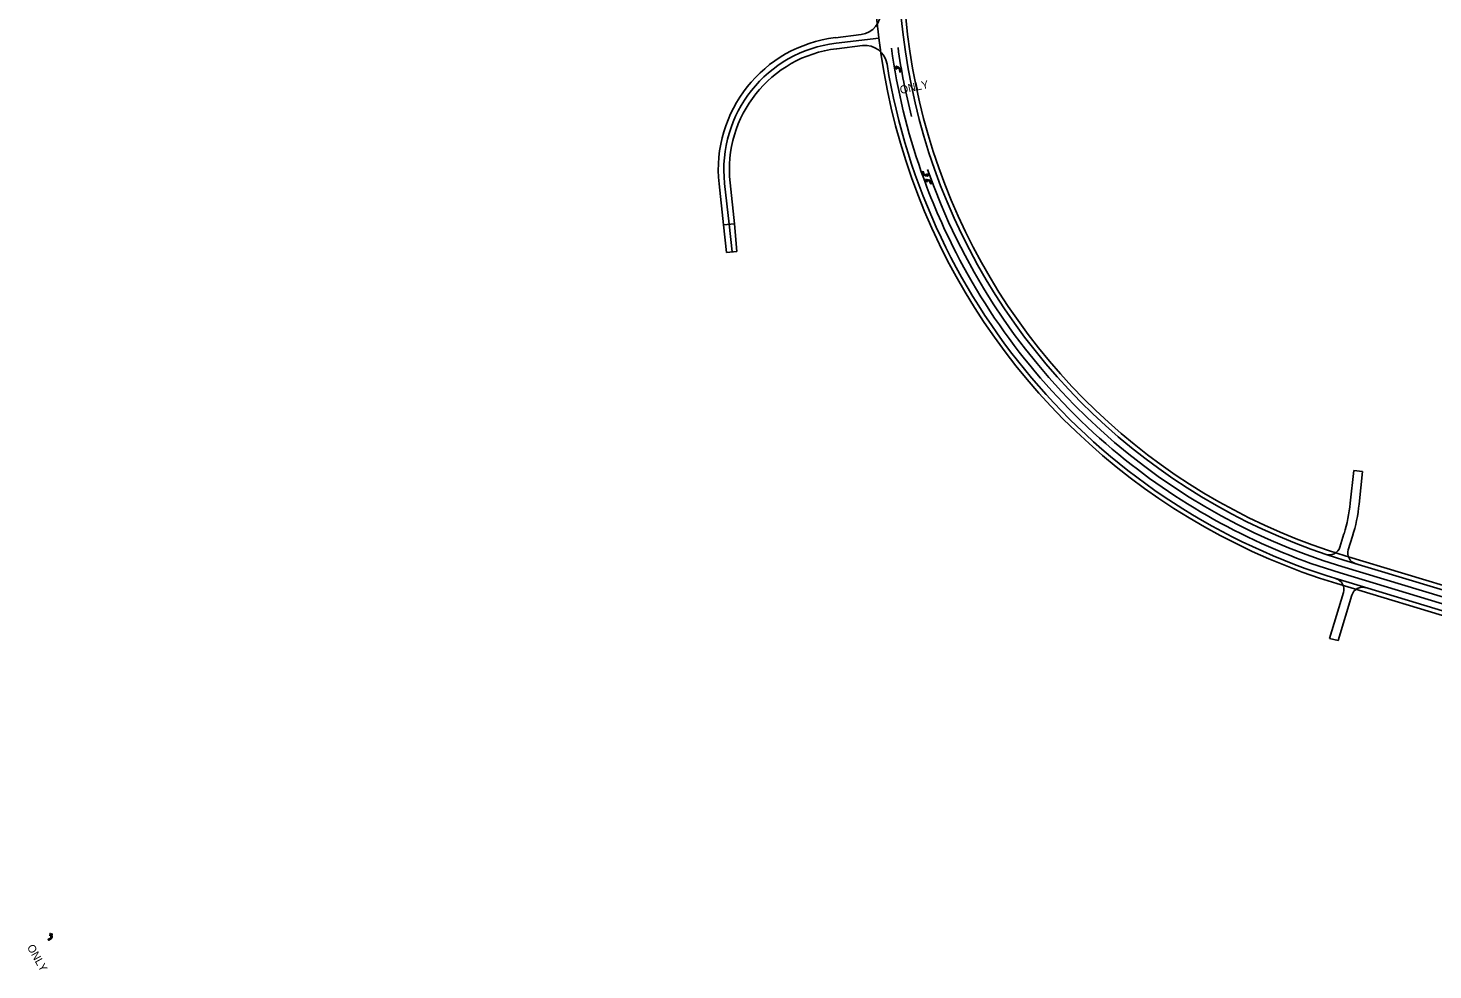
# Model space of a CAD drawing. Extents: x 979036 to 996074, y 1836928 to 1845163.
# Drawn here: x 979036 to 981565, y 1837762 to 1839457 of the extents above; entities that cross this region are included whole.
import ezdxf

# ---------------------------------------------------------------- set-up
doc = ezdxf.new("R2010")
doc.units = 0
for name, color, linetype in [('R_Proposed Road', 7, 'Continuous'), ('STRIPE_White Stopbar', 7, 'Continuous'), ('STRIPE_White Turn Arrow', 7, 'Continuous'), ('STRIPE_White_6in', 7, 'Continuous'), ('STRIPE_White_ONLY', 7, 'Continuous'), ('STRIPE_Yellow Dbl 6in', 7, 'Continuous'), ('STRIPE_Yellow_10_30 SKIP', 7, 'Continuous')]:
    doc.layers.add(name, color=color, linetype=linetype)

msp = doc.modelspace()

# ---------------------------------------------------------------- linework, layer by layer
at = {"layer": 'R_Proposed Road'}
for p, q in [((980288.1, 1839102.7), (980308, 1839104.8)), ((980293.4, 1839053), (980312.2, 1839055)), ((981416, 1838602), (981422.3, 1838660.9)), ((981438.2, 1838659.2), (981422.3, 1838660.9)), ((981431.9, 1838600.3), (981438.2, 1838659.2)), ((981397.3, 1838523), (981404.7, 1838547.1)), ((981412.5, 1838518.1), (981420, 1838542.4)), ((981406.9, 1838507.1), (983640.8, 1837831.3)), ((981403.7, 1838441.2), (981378.7, 1838358.7)), ((981391.8, 1838457.4), (983625.8, 1837781.5)), ((981419, 1838436.6), (981394.3, 1838354.8)), ((981378.7, 1838358.7), (981394.3, 1838354.8))]:
    msp.add_line(p, q, dxfattribs=at)
for centre, radius, start, end in [((981731.1, 1839579.1), 1171.9, 152.2175, 253.1679), ((981731.1, 1839579.1), 1119.9, 152.2175, 253.1679), ((981125.7, 1838633.1), 292, 342.87, 353.8875), ((981125.7, 1838633.1), 308, 342.87, 353.8875), ((981378.2, 1838528.9), 20, 251.4218, 342.87), ((981431.6, 1838512.2), 20, 162.87, 253.1679), ((981384.5, 1838447), 20, 343.1679, 72.9762), ((981438.1, 1838430.8), 20, 73.1679, 163.1679)]:
    msp.add_arc(centre, radius, start, end, dxfattribs=at)
at = {"layer": 'STRIPE_White Stopbar'}
msp.add_line((980570.4, 1839417.6), (980567.6, 1839438.9), dxfattribs=at)
at = {"layer": 'STRIPE_White Turn Arrow'}
for points in [[(980600.6, 1839383.1), (980596.6, 1839384.9), (980599.3, 1839388.3), (980599.7, 1839386.7), (980600.4, 1839386.8), (980601, 1839386.8), (980601.8, 1839386.8), (980602.8, 1839386.6), (980603.6, 1839386.3), (980604.2, 1839385.8), (980605, 1839385.3), (980605.5, 1839384.7), (980606, 1839384), (980606.4, 1839383.1), (980606.7, 1839382.1), (980607.2, 1839378.3), (980605.2, 1839378), (980604.7, 1839381.6), (980604.6, 1839382.2), (980604.3, 1839382.9), (980603.8, 1839383.7), (980603.1, 1839384.2), (980602.8, 1839384.4), (980602.1, 1839384.7), (980601.3, 1839384.8), (980600.6, 1839384.8), (980600.2, 1839384.8)], [(980653.2, 1839194.8), (980657.5, 1839194.1), (980655.7, 1839190.1), (980654.9, 1839191.6), (980654.3, 1839191.3), (980653.8, 1839191.1), (980653, 1839191), (980652, 1839191), (980651.1, 1839191.1), (980650.4, 1839191.3), (980649.5, 1839191.7), (980648.9, 1839192.1), (980648.2, 1839192.7), (980647.6, 1839193.4), (980647.1, 1839194.3), (980645.6, 1839197.9), (980647.5, 1839198.7), (980648.8, 1839195.3), (980649.1, 1839194.7), (980649.6, 1839194.1), (980650.3, 1839193.5), (980651, 1839193.2), (980651.4, 1839193.1), (980652.1, 1839192.9), (980652.9, 1839193), (980653.6, 1839193.2), (980654, 1839193.3)], [(980655.1, 1839180.2), (980650.8, 1839180.9), (980652.6, 1839184.9), (980653.4, 1839183.4), (980654, 1839183.7), (980654.6, 1839183.9), (980655.4, 1839184), (980656.4, 1839184.1), (980657.2, 1839184), (980658, 1839183.7), (980658.9, 1839183.4), (980659.5, 1839182.9), (980660.2, 1839182.4), (980660.8, 1839181.6), (980661.3, 1839180.7), (980662.7, 1839177.1), (980660.9, 1839176.4), (980659.5, 1839179.7), (980659.2, 1839180.3), (980658.7, 1839180.9), (980658.1, 1839181.5), (980657.3, 1839181.9), (980656.9, 1839181.9), (980656.2, 1839182.1), (980655.4, 1839182), (980654.7, 1839181.8), (980654.3, 1839181.7)], [(979075.7, 1837823.5), (979075.9, 1837827.8), (979080.1, 1837826.5), (979078.7, 1837825.5), (979079, 1837825), (979079.3, 1837824.4), (979079.5, 1837823.7), (979079.7, 1837822.7), (979079.6, 1837821.8), (979079.5, 1837821), (979079.2, 1837820.1), (979078.8, 1837819.4), (979078.4, 1837818.7), (979077.7, 1837818), (979076.9, 1837817.4), (979073.5, 1837815.6), (979072.5, 1837817.3), (979075.7, 1837819), (979076.3, 1837819.4), (979076.8, 1837820), (979077.3, 1837820.7), (979077.6, 1837821.5), (979077.6, 1837821.9), (979077.6, 1837822.6), (979077.5, 1837823.4), (979077.2, 1837824.1), (979077.1, 1837824.4)]]:
    msp.add_lwpolyline(points, close=True, dxfattribs=at)
at = {"layer": 'STRIPE_White_6in'}
for p, q in [((980489.3, 1839439.5), (980535.7, 1839445.1)), ((980491.7, 1839419.7), (980538.1, 1839425.3)), ((980288.1, 1839102.7), (980280.1, 1839176.3)), ((980308, 1839104.8), (980300, 1839178.5)), ((980288.1, 1839102.7), (980293.4, 1839053)), ((980308, 1839104.8), (980312.2, 1839055)), ((981404.5, 1838499.5), (983638.5, 1837823.6)), ((981394.1, 1838465), (983628.1, 1837789.2))]:
    msp.add_line(p, q, dxfattribs=at)
for centre, radius, start, end in [((981731.1, 1839579.1), 1127.9, 152.2175, 253.1679), ((980530.9, 1839484.8), 40, 276.8699, 4.4896), ((980517.9, 1839202.1), 239.2, 96.8699, 186.1831), ((980542.9, 1839385.6), 40, 9.2501, 96.8699), ((981731.1, 1839579.1), 1139.9, 187.9186, 194.2764), ((980517.9, 1839202.1), 219.2, 96.8699, 186.1831), ((981731.1, 1839579.1), 1163.9, 189.2501, 253.1679)]:
    msp.add_arc(centre, radius, start, end, dxfattribs=at)
at = {"layer": 'STRIPE_Yellow Dbl 6in'}
for p, q in [((980490.5, 1839429.6), (980567.6, 1839438.9)), ((980298.1, 1839103.8), (980290.1, 1839177.4)), ((980303.4, 1839054), (980298.1, 1839103.8))]:
    msp.add_line(p, q, dxfattribs=at)
for centre, radius, start, end in [((980517.9, 1839202.1), 229.2, 96.8699, 186.1831), ((981731.1, 1839579.1), 1151.9, 187.9186, 199.3058)]:
    msp.add_arc(centre, radius, start, end, dxfattribs=at)
at = {"layer": 'STRIPE_Yellow_10_30 SKIP'}
for p, q in [((981401.1, 1838488), (983635, 1837812.2)), ((981401.1, 1838488), (983635, 1837812.2)), ((983631.6, 1837800.7), (981397.6, 1838476.5)), ((981397.6, 1838476.5), (983631.6, 1837800.7))]:
    msp.add_line(p, q, dxfattribs=at)
for radius, start, end in [(1151.9, 199.3058, 207.197), (1151.9, 199.3058, 207.197), (1139.9, 199.3028, 253.1679), (1139.9, 199.3028, 253.1679), (1151.9, 207.197, 231.3148), (1151.9, 207.197, 231.3148), (1151.9, 231.3147, 253.1679), (1151.9, 231.3147, 253.1679)]:
    msp.add_arc((981731.1, 1839579.1), radius, start, end, dxfattribs=at)

# ---------------------------------------------------------------- texts
at = {"layer": 'STRIPE_White_ONLY'}
for rotation, p in [(11.9317, (980606.9, 1839338.2)), (299.143, (979034, 1837803.3))]:
    msp.add_text('ONLY', height=14.4, rotation=rotation, dxfattribs=at).set_placement(p)

doc.saveas('drawing.dxf')
